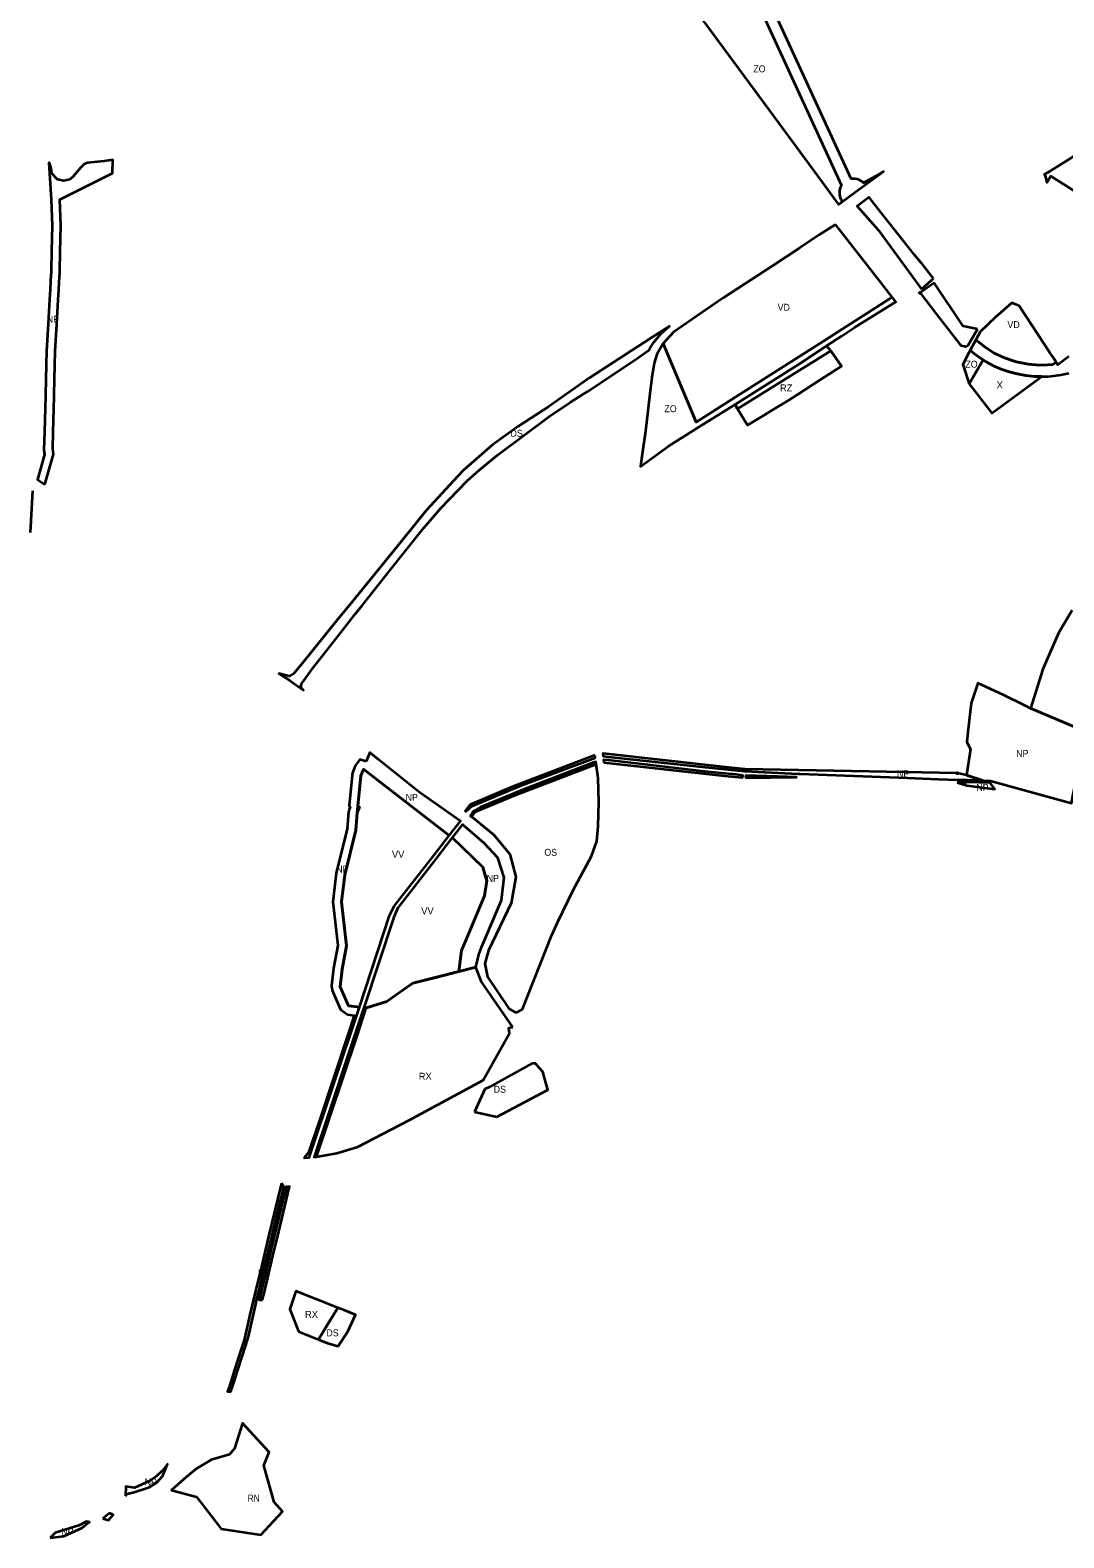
# Model space of a CAD drawing. Extents: x -650276 to -642489, y -1074311 to -1066658.
# Drawn here: x -649013 to -647227, y -1074311 to -1071706 of the extents above; entities that cross this region are included whole.
import ezdxf

# ---------------------------------------------------------------- set-up
doc = ezdxf.new("R2010")
doc.units = 0
doc.header["$LTSCALE"] = 4.8
doc.header["$PDMODE"] = 32
doc.header["$PDSIZE"] = 2.4
for name, color, linetype, lineweight in [('15', 7, 'Continuous', 35), ('24', 7, 'Continuous', 35), ('35', 7, 'Continuous', 35), ('42', 7, 'Continuous', 35), ('45', 7, 'Continuous', 35), ('48', 7, 'Continuous', 35), ('5', 7, 'Continuous', 35), ('51', 7, 'Continuous', 35), ('54', 7, 'Continuous', 35), ('7', 7, 'Continuous', 35), ('8', 7, 'Continuous', 35), ('9', 7, 'Continuous', 35)]:
    doc.layers.add(name, color=color, linetype=linetype, lineweight=lineweight)
doc.layers.add('62', color=7, linetype='Continuous')
doc.layers.add('63', color=7, linetype='Continuous')

msp = doc.modelspace()

# ---------------------------------------------------------------- linework, layer by layer
at = {"layer": '15'}
msp.add_lwpolyline([(-647795.4, -1072352.415), (-647679.66, -1072279.15), (-647637.082, -1072251.377), (-647629.67, -1072259.82), (-647791.198, -1072360.119)], close=True, dxfattribs=at)
for points in [[(-647629.67, -1072259.82), (-647637.082, -1072251.377), (-647679.66, -1072279.15)], [(-647679.66, -1072279.15), (-647795.4, -1072352.415), (-647791.198, -1072360.119), (-647629.67, -1072259.82)]]:
    msp.add_lwpolyline(points, dxfattribs=at)
at = {"layer": '24'}
msp.add_line((-648245.341, -1073575.152), (-648207, -1073584), dxfattribs=at)
for points in [[(-647782.97, -1071619.278), (-647769.498, -1071636.647), (-647758.994, -1071653.513), (-647743.48, -1071687.426), (-647611.514, -1071974.086)], [(-647570.747, -1071972.644), (-647538.922, -1071950.099), (-647551.962, -1071958.049), (-647573.283, -1071969.627), (-647575.415, -1071967.709), (-647577.881, -1071965.979), (-647581.036, -1071964.346), (-647584.363, -1071963.196), (-647588.064, -1071962.51), (-647591.518, -1071962.387), (-647594.731, -1071962.714), (-647725.614, -1071678.405), (-647726.774, -1071675.885), (-647725.629, -1071678.373)], [(-647611.514, -1071974.086), (-647613.455, -1071978.031), (-647614.654, -1071982.238), (-647615.083, -1071986.65), (-647614.76, -1071990.762), (-647613.637, -1071995.081), (-647611.779, -1071999.069), (-647609.808, -1072001.962), (-647570.747, -1071972.644)], [(-647542.57, -1072021.99), (-647558.97, -1072000.62), (-647563.77, -1071994.38), (-647579.885, -1072006.501)], [(-647579.885, -1072006.501), (-647584.202, -1072009.747), (-647547.916, -1072050.439), (-647473.022, -1072153.375)], [(-647452.23, -1072134.91), (-647472.86, -1072109.13), (-647474.72, -1072106.81), (-647485.6, -1072093.2), (-647504.73, -1072069.29), (-647542.57, -1072021.99)], [(-647451.21, -1072142.08), (-647473.12, -1072157.91), (-647475.57, -1072159.74), (-647475.57, -1072159.74)], [(-647473.022, -1072153.375), (-647455.83, -1072137.96), (-647452.23, -1072134.91)], [(-647376.68, -1072222.29), (-647401.221, -1072217.342), (-647451.21, -1072142.08)], [(-647475.57, -1072159.74), (-647447.73, -1072195.72), (-647407.34, -1072247.93)], [(-647407.34, -1072247.93), (-647404.45, -1072250.66), (-647396.25, -1072252.14), (-647392.34, -1072250.02), (-647376.68, -1072222.29)], [(-647218.35, -1072269.67), (-647237.6, -1072283.78), (-647240.55, -1072279.42), (-647246.206, -1072283.328), (-647255.671, -1072284.192), (-647269.579, -1072284.489), (-647288.769, -1072283.003), (-647309.416, -1072278.875), (-647330.032, -1072271.935), (-647347.382, -1072263.623), (-647363.317, -1072253.632), (-647379.422, -1072240.675), (-647389.072, -1072258.845), (-647383.813, -1072263.219), (-647372.858, -1072271.363), (-647361.521, -1072278.584), (-647347.369, -1072286.111), (-647335.382, -1072291.341), (-647321.953, -1072296.073), (-647308.157, -1072299.786), (-647292.715, -1072302.646), (-647278.108, -1072304.147), (-647271.395, -1072304.452), (-647265.793, -1072304.439), (-647265.793, -1072304.439), (-647255.16, -1072304.123), (-647244.428, -1072303.192), (-647232.368, -1072301.4), (-647218.5, -1072298.335)], [(-648139.56, -1073491.4), (-648146.4, -1073491.55), (-648220.42, -1073532.43), (-648227.63, -1073535.89), (-648245.341, -1073575.152)], [(-648207, -1073584), (-648119, -1073537), (-648127.31, -1073505.75), (-648138.41, -1073493.62), (-648139.56, -1073491.4)]]:
    msp.add_lwpolyline(points, dxfattribs=at)
for points in [[(-648303.791, -1072531.792), (-648258.165, -1072484.283), (-648237.406, -1072465.811), (-648205.298, -1072439.308), (-648116.32, -1072373.44), (-648079.76, -1072348.46), (-648050.276, -1072330.025), (-647969.894, -1072276.479), (-647944.45, -1072258.458), (-647941.77, -1072254.45), (-647934.9, -1072244.55), (-647923.16, -1072229.85), (-647908.5, -1072217.29), (-647933.95, -1072233.18), (-647942.21, -1072238.54), (-648046.69, -1072306.3), (-648117.12, -1072356), (-648169.81, -1072390.035), (-648214.73, -1072422.41), (-648264.618, -1072466.244), (-648274.53, -1072476.196), (-648328.847, -1072535.816), (-648369.37, -1072585.645), (-648431.557, -1072662.77), (-648459.243, -1072696.417), (-648481.468, -1072723.736), (-648543.255, -1072800.016), (-648557.588, -1072817.727), (-648565.726, -1072822.048), (-648583.407, -1072817.256), (-648564.86, -1072829.45), (-648554.22, -1072836.89), (-648541.102, -1072846.281), (-648545.462, -1072840.329), (-648544.632, -1072835.177), (-648524.979, -1072808.383), (-648507.503, -1072786.605), (-648476.204, -1072746.1), (-648452.274, -1072715.637), (-648439.912, -1072699.826), (-648391.796, -1072639.344), (-648333.178, -1072565.837)], [(-648515.333, -1073968.584), (-648499.84, -1073974.76), (-648480.86, -1073980.25), (-648464.44, -1073954.69), (-648451.05, -1073925.87), (-648471, -1073918), (-648481.749, -1073913.76)]]:
    msp.add_lwpolyline(points, close=True, dxfattribs=at)
msp.add_point((-647475.57, -1072159.74), dxfattribs=at)
at = {"layer": '35'}
for points in [[(-647194.903, -1071913.941), (-647238.1, -1071941), (-647245.71, -1071945.77), (-647253.67, -1071950.76), (-647261.12, -1071954.82), (-647259.7, -1071957.06), (-647256.53, -1071968.64), (-647253.85, -1071964.38), (-647249.92, -1071958.12), (-647201.53, -1071988.71)], [(-647621.97, -1072041.73), (-647649.76, -1072059.06), (-647683.63, -1072081.94), (-647730.53, -1072112.84), (-647814.58, -1072167.67), (-647845.58, -1072188.94), (-647901.91, -1072227.6), (-647919.68, -1072247.09), (-647862.615, -1072383.084)], [(-647523.71, -1072167.071), (-647545.44, -1072139.35), (-647621.97, -1072041.73)], [(-647862.615, -1072383.084), (-647800.2, -1072343.615), (-647642.504, -1072242.974), (-647616.719, -1072226.154), (-647523.71, -1072167.071)]]:
    msp.add_lwpolyline(points, dxfattribs=at)
msp.add_lwpolyline([(-647246.563, -1072270.214), (-647251.85, -1072262.12), (-647271.38, -1072232.23), (-647304.32, -1072181.81), (-647310.33, -1072179.58), (-647317.33, -1072176.99), (-647345.42, -1072201.58), (-647372.1, -1072226.89), (-647375.551, -1072233.387), (-647379.422, -1072240.675), (-647363.317, -1072253.632), (-647347.382, -1072263.623), (-647330.032, -1072271.935), (-647309.416, -1072278.875), (-647288.769, -1072283.003), (-647269.579, -1072284.489), (-647255.671, -1072284.192), (-647246.206, -1072283.328), (-647240.55, -1072279.42)], close=True, dxfattribs=at)
at = {"layer": '42'}
for points in [[(-647743.48, -1071687.426), (-647611.514, -1071974.086), (-647613.455, -1071978.031), (-647614.654, -1071982.238), (-647615.083, -1071986.65), (-647614.76, -1071990.762), (-647613.637, -1071995.081), (-647611.779, -1071999.069), (-647609.808, -1072001.962), (-647616.12, -1072006.7), (-647621.06, -1072000), (-647644.38, -1071968.3), (-647705.291, -1071885.501), (-647727.85, -1071854.86), (-647857.52, -1071678.92)], [(-647637.082, -1072251.377), (-647611.306, -1072234.563), (-647589.02, -1072219.66), (-647517.51, -1072174.98), (-647523.71, -1072167.071), (-647616.719, -1072226.154), (-647642.504, -1072242.974), (-647800.2, -1072343.615)], [(-647800.2, -1072343.615), (-647862.615, -1072383.084), (-647919.68, -1072247.09), (-647930.36, -1072266.38), (-647934.86, -1072280.99), (-647939.26, -1072306.1), (-647942.54, -1072333.82), (-647950.2, -1072398.61), (-647956.786, -1072446.511), (-647958.82, -1072459.74), (-647910.27, -1072424.51), (-647857.52, -1072391.14), (-647795.4, -1072352.415)], [(-647795.4, -1072352.415), (-647679.66, -1072279.15), (-647637.082, -1072251.377)]]:
    msp.add_lwpolyline(points, dxfattribs=at)
msp.add_lwpolyline([(-647390.58, -1072316.75), (-647366.505, -1072275.41), (-647372.858, -1072271.363), (-647383.813, -1072263.219), (-647389.072, -1072258.845), (-647391.3, -1072263.04), (-647401.88, -1072283.4)], close=True, dxfattribs=at)
at = {"layer": '45'}
for points in [[(-648463.25, -1073392.125), (-648444.523, -1073394.235), (-648392.43, -1073235.98), (-648384.6, -1073219.54), (-648315.955, -1073131.889), (-648289.148, -1073097.66), (-648437.643, -1072982.601), (-648442.187, -1072994.5), (-648447.043, -1073046.967), (-648444.11, -1073048.69), (-648448.1, -1073058.393)], [(-648448.1, -1073058.393), (-648450.875, -1073088.375), (-648469.875, -1073165.5), (-648475.437, -1073212.375), (-648466.687, -1073288.25), (-648474.5, -1073328.75), (-648477.562, -1073358.875), (-648463.25, -1073392.125)], [(-648272.642, -1073332.558), (-648268, -1073296), (-648261, -1073280), (-648228, -1073202), (-648224, -1073176), (-648231, -1073152), (-648283.884, -1073101.15), (-648311.798, -1073137.127), (-648378.17, -1073222.67), (-648385.09, -1073238.58), (-648436.857, -1073395.099)], [(-648397.062, -1073384.375), (-648378.125, -1073370.875), (-648352.312, -1073353), (-648314.687, -1073343.25), (-648272.642, -1073332.558)], [(-648436.857, -1073395.099), (-648432.187, -1073395.625), (-648397.062, -1073384.375)]]:
    msp.add_lwpolyline(points, dxfattribs=at)
at = {"layer": '48'}
for points in [[(-648988.248, -1072491.089), (-648973.238, -1072438.27), (-648974.424, -1072429.462), (-648973.655, -1072400.254), (-648972.605, -1072360.164), (-648972.025, -1072338.183), (-648971.955, -1072335.341), (-648970.605, -1072283.823), (-648970.001, -1072260.788), (-648967.285, -1072213.663), (-648964.865, -1072171.684), (-648963.895, -1072154.905), (-648963.052, -1072140.301), (-648962.27, -1072125.223), (-648962.165, -1072120.949), (-648961.355, -1072088.12), (-648960.263, -1072043.893), (-648962.195, -1071998.309), (-648871.27, -1071952.643), (-648870.458, -1071929.441), (-648885.56, -1071932.1), (-648914.45, -1071934.78), (-648919.79, -1071937.27), (-648925.64, -1071943.18), (-648939.51, -1071959.25), (-648944.69, -1071963.44), (-648955.25, -1071966.15), (-648966.01, -1071963.74), (-648975.65, -1071953.47), (-648976.85, -1071944.78), (-648979.85, -1071935.11), (-648980.94, -1071935.12), (-648977.48, -1071989.2), (-648976.91, -1071998.2), (-648975.27, -1072044.01), (-648976.35, -1072087.75), (-648977.16, -1072120.58), (-648977.26, -1072124.65), (-648977.3, -1072126.08), (-648977.33, -1072127.34), (-648978.03, -1072139.48), (-648978.87, -1072154.04), (-648979.84, -1072170.82), (-648982.26, -1072212.8), (-648984.99, -1072260.16), (-648985.6, -1072283.43), (-648986.31, -1072310.66), (-648986.95, -1072334.96), (-648987.02, -1072337.8), (-648987.6, -1072359.77), (-648988.65, -1072399.86), (-648989.45, -1072430.27), (-648988.27, -1072439.04), (-649000.851, -1072482.138)], [(-647293.317, -1072873.549), (-647293.351, -1072873.533), (-647331.82, -1072854.49), (-647375.92, -1072833.99), (-647387.64, -1072868.69), (-647392.96, -1072918.277), (-647394.87, -1072936.08), (-647388.62, -1072948.03), (-647395.47, -1072993.25), (-647367.45, -1073002.47), (-647353.78, -1073003.1), (-647213.99, -1073041.449), (-647210.396, -1073023.593), (-647207.176, -1073007.598), (-647192.93, -1072936.82), (-647187.445, -1072918.804), (-647192.718, -1072916.582), (-647282.31, -1072878.82), (-647284.75, -1072877.79)], [(-648037.595, -1072959.123), (-648038.877, -1072959.418), (-648180.651, -1073013.629), (-648253.635, -1073044.348), (-648261.902, -1073054.939), (-648260.27, -1073056.17), (-648250.04, -1073047.08), (-648178.89, -1073017.03), (-648165.13, -1073011.22), (-648037.17, -1072963.24)], [(-648251.027, -1073065.418), (-648250.491, -1073064.698), (-648244.214, -1073056.657), (-648175.061, -1073027.551), (-648035.592, -1072974.222), (-648036.2, -1072969.98), (-648040.06, -1072971.47), (-648161.07, -1073017.9), (-648235.47, -1073048.4), (-648247.16, -1073055.34), (-648252.64, -1073064.13)], [(-648022.279, -1072971.102), (-647813.331, -1072994.317), (-647782.72, -1072997.397), (-647781.65, -1072993.53), (-647793.59, -1072992.29), (-647813.2, -1072990.26), (-647848.15, -1072986.63), (-648014.58, -1072967.51), (-648022.74, -1072966.57)], [(-647777.337, -1072997.711), (-647689.11, -1072996.49), (-647721.83, -1072995.45), (-647776.77, -1072993.69)], [(-647411.34, -1073005.89), (-647394.782, -1073011.002), (-647346.22, -1073017.52), (-647354.76, -1073006.65), (-647394.59, -1073005.58), (-647395.08, -1073005.64), (-647397.74, -1073005.95), (-647400.27, -1073006.24), (-647400.76, -1073006.29), (-647403.05, -1073006.2)], [(-648231, -1073152), (-648224, -1073176), (-648228, -1073202), (-648261, -1073280), (-648268, -1073296), (-648272.642, -1073332.558), (-648243.08, -1073325.04), (-648237.98, -1073303.4), (-648232.64, -1073289.31), (-648198.7, -1073209.08), (-648194.2, -1073170.13), (-648205.04, -1073136.07), (-648228.91, -1073110.54), (-648266.38, -1073078.59), (-648283.884, -1073101.15)], [(-648518.867, -1073652.836), (-648499.399, -1073594.679), (-648449.599, -1073445.278), (-648433.206, -1073395.51), (-648436.857, -1073395.099), (-648440.74, -1073406.84), (-648517.47, -1073637.26), (-648522.79, -1073653.23), (-648518.867, -1073652.836)], [(-648612.186, -1073900.905), (-648609.231, -1073888.415), (-648599.275, -1073846.445), (-648592.044, -1073816.692), (-648586.715, -1073794.059), (-648565.224, -1073704.393), (-648565.224, -1073704.393), (-648570.99, -1073704.56), (-648571.72, -1073707.63), (-648573.46, -1073714.88), (-648576.05, -1073725.82), (-648579.57, -1073740.47), (-648592.17, -1073793.18), (-648597.23, -1073814.32), (-648601.98, -1073834.2), (-648606.83, -1073854.48), (-648613.78, -1073883.59), (-648617.72, -1073900.06)], [(-648848.696, -1074238.993), (-648845.424, -1074235.305), (-648833.449, -1074232.685), (-648807.065, -1074223.704), (-648794.902, -1074216.219), (-648783.863, -1074204.056), (-648775.93, -1074183.91), (-648784.8, -1074195.26), (-648795.65, -1074205.35), (-648806.55, -1074212.62), (-648833.11, -1074225.2), (-648844.05, -1074223.24), (-648848.28, -1074222.49)], [(-648978.575, -1074311.426), (-648955.265, -1074308.325), (-648923.698, -1074294.313), (-648912.63, -1074284.912), (-648910.988, -1074284.211), (-648915.73, -1074283.08), (-648929.03, -1074290.14), (-648970.3, -1074302.9)], [(-648887.619, -1074278.134), (-648877.799, -1074280.64), (-648870.041, -1074271.932), (-648876.21, -1074268.73)]]:
    msp.add_lwpolyline(points, close=True, dxfattribs=at)
for points in [[(-648437.643, -1072982.601), (-648289.148, -1073097.66), (-648269.78, -1073072.93), (-648339.58, -1073023.82), (-648341.495, -1073022.285), (-648411.09, -1072966.5), (-648426.547, -1072954.108), (-648432.527, -1072969.463)], [(-647685.748, -1072984.544), (-647778.296, -1072982.767), (-647811.752, -1072979.4), (-648023.495, -1072955.875), (-648023.818, -1072955.949), (-648023.37, -1072960.37), (-648014.16, -1072961.36), (-647846.85, -1072979.37), (-647790.52, -1072985.06), (-647778.3, -1072986.29), (-647686.14, -1072990.78)], [(-648432.527, -1072969.463), (-648443.591, -1072965.983), (-648451.657, -1072977.25), (-648456.2, -1072989.149), (-648457.123, -1072993.118), (-648461.979, -1073045.585), (-648460.355, -1073048.753), (-648461.973, -1073052.688), (-648463.036, -1073057.011), (-648465.708, -1073085.876), (-648484.661, -1073162.812), (-648490.539, -1073212.35), (-648481.853, -1073287.675), (-648489.355, -1073326.567), (-648492.485, -1073357.358), (-648491.34, -1073364.805), (-648477.028, -1073398.055), (-648464.929, -1073407.031), (-648453.228, -1073408.349), (-648463.838, -1073440.559), (-648513.627, -1073589.927), (-648532.252, -1073645.567), (-648539.599, -1073654.802), (-648531.31, -1073654.08), (-648444.523, -1073394.235), (-648448.434, -1073393.794), (-648463.25, -1073392.125), (-648477.562, -1073358.875), (-648474.5, -1073328.75), (-648466.687, -1073288.25), (-648475.437, -1073212.375), (-648469.875, -1073165.5), (-648450.875, -1073088.375), (-648448.1, -1073058.393), (-648447.043, -1073046.967), (-648442.187, -1072994.5), (-648437.643, -1072982.601)], [(-647411.294, -1072989.813), (-647411.298, -1072989.813), (-647685.748, -1072984.544)], [(-647686.14, -1072990.78), (-647682.74, -1072990.95), (-647497.35, -1072997.93), (-647444.42, -1072999.87), (-647411.326, -1073001.08)], [(-647411.326, -1073001.08), (-647410.791, -1073001.197), (-647410.79, -1073001.1), (-647402.49, -1073001.41), (-647400.55, -1073001.48), (-647394.46, -1073001.23), (-647367.45, -1073002.47), (-647395.47, -1072993.25), (-647411.293, -1072989.813), (-647411.294, -1072989.813)], [(-648579.272, -1073698.648), (-648601.309, -1073790.592), (-648606.633, -1073813.202), (-648613.86, -1073842.943), (-648623.827, -1073884.957), (-648633.591, -1073926.228), (-648643.415, -1073969.782), (-648647.944, -1073983.639), (-648660.613, -1074022.822), (-648664.22, -1074034.155)], [(-648659.85, -1074037.72), (-648655.5, -1074024.36), (-648645.7, -1073994.3), (-648638.15, -1073971.13), (-648636.34, -1073963.19), (-648628.21, -1073927.61), (-648623.58, -1073907.34), (-648622.06, -1073901.02), (-648617.77, -1073883.09), (-648616.76, -1073878.91), (-648611.69, -1073857.74), (-648607.72, -1073841.19), (-648607.4, -1073839.84), (-648595.71, -1073791.1), (-648588.06, -1073759.19), (-648584.69, -1073745.15), (-648581.82, -1073733.14), (-648578.69, -1073720.11), (-648574.99, -1073704.67), (-648579.272, -1073698.648)], [(-648664.22, -1074034.155), (-648669.584, -1074051.005), (-648672.336, -1074058.391), (-648672.336, -1074058.391), (-648666.67, -1074058.64), (-648659.85, -1074037.72)]]:
    msp.add_lwpolyline(points, dxfattribs=at)
msp.add_point((-647411.294, -1072989.813), dxfattribs=at)
at = {"layer": '5'}
for points in [[(-648272.642, -1073332.558), (-648352.312, -1073353), (-648397.062, -1073384.375)], [(-648179.07, -1073428.81), (-648233.36, -1073350.68), (-648243.08, -1073325.04), (-648272.642, -1073332.558)], [(-648397.062, -1073384.375), (-648432.187, -1073395.625), (-648433.206, -1073395.51), (-648449.599, -1073445.278)], [(-648449.599, -1073445.278), (-648518.867, -1073652.836), (-648483.58, -1073646.7), (-648447.06, -1073635.39), (-648447.06, -1073635.39)], [(-648447.06, -1073635.39), (-648358.69, -1073589.35), (-648230.81, -1073520.18), (-648185.34, -1073438.91), (-648185.82, -1073435.12), (-648186.46, -1073430.01), (-648183.46, -1073429.52), (-648179.07, -1073428.81)]]:
    msp.add_lwpolyline(points, dxfattribs=at)
msp.add_lwpolyline([(-648549.76, -1073954.86), (-648515.333, -1073968.584), (-648498, -1073940), (-648481.749, -1073913.76), (-648554.42, -1073885.092), (-648564.75, -1073915.91)], close=True, dxfattribs=at)
at = {"layer": '51'}
msp.add_lwpolyline([(-647390.58, -1072316.75), (-647351.86, -1072367.52), (-647269.52, -1072307.17), (-647265.793, -1072304.439), (-647271.395, -1072304.452), (-647278.108, -1072304.147), (-647292.715, -1072302.646), (-647308.157, -1072299.786), (-647321.953, -1072296.073), (-647335.382, -1072291.341), (-647347.369, -1072286.111), (-647361.521, -1072278.584), (-647366.505, -1072275.41)], close=True, dxfattribs=at)
msp.add_lwpolyline([(-647212.92, -1072708.05), (-647236.54, -1072748.09), (-647252.29, -1072783.24), (-647263.58, -1072809.97), (-647284.75, -1072877.79), (-647282.31, -1072878.82), (-647192.718, -1072916.582), (-647192.069, -1072916.856)], dxfattribs=at)
at = {"layer": '54'}
msp.add_line((-649009.031, -1072501.969), (-649013.32, -1072573.664), dxfattribs=at)
at = {"layer": '7'}
msp.add_lwpolyline([(-648725.93, -1074240.58), (-648683.5, -1074296.12), (-648683.5, -1074296.12), (-648614.6, -1074306.17), (-648577.25, -1074266.06), (-648591.67, -1074249.72), (-648609.49, -1074186.61), (-648600.53, -1074163.47), (-648646.42, -1074113.19), (-648660.16, -1074156.75), (-648669.01, -1074167.27), (-648700.45, -1074176.73), (-648726.23, -1074192.02), (-648747.74, -1074210.12), (-648768.94, -1074229.25), (-648725.93, -1074240.58), (-648725.93, -1074240.58)], close=True, dxfattribs=at)
at = {"layer": '8'}
msp.add_lwpolyline([(-647629.67, -1072259.82), (-647611.51, -1072286.26), (-647648.09, -1072309.95), (-647688.26, -1072336.06), (-647702.35, -1072345.14), (-647716.62, -1072353.95), (-647730.97, -1072362.6), (-647745.32, -1072371.26), (-647759.68, -1072379.91), (-647774.04, -1072388.57), (-647791.198, -1072360.119)], close=True, dxfattribs=at)
for points in [[(-647629.67, -1072259.82), (-647791.198, -1072360.119), (-647774.04, -1072388.57)], [(-647774.04, -1072388.57), (-647759.68, -1072379.91), (-647745.32, -1072371.26), (-647730.97, -1072362.6), (-647716.62, -1072353.95), (-647702.35, -1072345.14), (-647688.26, -1072336.06), (-647648.09, -1072309.95), (-647611.51, -1072286.26), (-647629.67, -1072259.82)]]:
    msp.add_lwpolyline(points, dxfattribs=at)
at = {"layer": '9'}
for points in [[(-648030.86, -1073039.71), (-648032.09, -1072998.65), (-648035.592, -1072974.222), (-648175.061, -1073027.551), (-648244.214, -1073056.657), (-648250.491, -1073064.698), (-648212.22, -1073096.39), (-648184.37, -1073129.89)], [(-648101.67, -1073246.63), (-648075.34, -1073191.93), (-648043.29, -1073132.97), (-648034.43, -1073107.07), (-648031.8, -1073082.07), (-648030.86, -1073039.71)], [(-648184.37, -1073129.89), (-648174.03, -1073168.94), (-648182.12, -1073214.56), (-648221.39, -1073296.24), (-648227.75, -1073318.75), (-648223.03, -1073341.59), (-648186.47, -1073396.47), (-648173.38, -1073404.03)], [(-648173.38, -1073404.03), (-648162.55, -1073397.4), (-648112.36, -1073270.87), (-648101.67, -1073246.63)]]:
    msp.add_lwpolyline(points, dxfattribs=at)

# ---------------------------------------------------------------- texts
at = {"layer": '62'}
for s, width, p in [('ZO', 0.95, (-647763.886, -1071778.486)), ('NP', 0.95, (-648984.583, -1072211.041)), ('VD', 0.95, (-647721.74, -1072190.495)), ('VD', 0.95, (-647324.74, -1072220.495)), ('ZO', 0.95, (-647397.457, -1072288.915)), ('ZO', 0.95, (-647917.457, -1072365.915)), ('NP', 0.95, (-647309.627, -1072961.756)), ('NP', 0.95, (-647515.505, -1072996.594)), ('NP', 0.95, (-647378.505, -1073020.594)), ('NP', 0.95, (-648364.505, -1073037.594)), ('OS', 0.95, (-648124.882, -1073132.612)), ('NP', 0.95, (-648484.505, -1073161.594)), ('NP', 0.95, (-648224.505, -1073177.594)), ('DS', 0.95, (-648212.386, -1073542.148)), ('NP', 0.95, (-648619.524, -1073859.849)), ('DS', 0.95, (-648501.386, -1073963.148)), ('NP', 0.95, (-648815.524, -1074220.849)), ('RN', 0.9, (-648637.627, -1074248.756)), ('NP', 0.95, (-648959.524, -1074306.849))]:
    msp.add_text(s, height=12, dxfattribs=dict(at, width=width)).set_placement(p)
for s, p in [('RZ', (-647717.713, -1072329.92)), ('X', (-647343.371, -1072324.801)), ('VV', (-648388.203, -1073135.952)), ('VV', (-648337.553, -1073233.772)), ('RX', (-648341.882, -1073519.612)), ('RX', (-648538.32, -1073931.277))]:
    msp.add_text(s, height=12, dxfattribs=at).set_placement(p)
at = {"layer": '63', "width": 0.95}
msp.add_text('DS', height=12, dxfattribs=at).set_placement((-648183.378, -1072408.379))

doc.saveas('drawing.dxf')
